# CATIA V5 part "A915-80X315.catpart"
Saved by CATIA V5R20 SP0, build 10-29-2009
Part number: A915-80X315
Source: Unknown
Property "A": "0.000"
Property "ARTICLENO": "A915-80X315"
Property "BOMINFO": "A915-80X315"
Property "CODE": "A915-80X315"
Property "CREATOR": "CADENAS GmbH"
Property "D": "13.500"
Property "D1": "20.000"
Property "FORM": "B"
Property "L": "315.000"
Property "L1": "40.000"
Property "L2": "235.000"
Property "LINA": "A915-80X315"
Property "NB": "A915-80X315"
Property "NBSYN": "$CODE."
Property "NN": "A915"
Property "NT": "VDI 3357 Wear Plates, steel"
Property "SCREW": "M12x25"
Property "SUPPLIER": "CF"
Property "T": "13.000"
Property "W": "80.000"
Bounding box of the stored display mesh (mm): x 0 to 20, y 0 to 315, z -40 to 40
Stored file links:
  C:\Users\borellobunino\Desktop\3D X SITO CF\A915\GSB_OILLESS_G22501080315\CATIAV5\A915-80X315.catpart
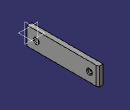
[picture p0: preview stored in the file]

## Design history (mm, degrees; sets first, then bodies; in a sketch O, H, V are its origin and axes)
Body1 "Geometry.1" (main body)
  Solid1 "A915-80X315.catpart": solid without history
